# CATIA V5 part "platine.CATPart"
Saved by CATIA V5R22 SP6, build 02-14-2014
Part number: platine
Bounding box of the stored display mesh (mm): x -45 to 45, y -36 to 36, z 0 to 8
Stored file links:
  C:\Users\kremer\Desktop\demo_5x\platine.CATPart
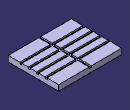
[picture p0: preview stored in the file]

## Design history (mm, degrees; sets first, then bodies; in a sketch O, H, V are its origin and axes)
Body1 (main body)
  Sketch1 on xy-plane, origin (0, 0, 0), H (1, 0, 0), V (0, 1, 0)
    line L1 (45, 36) -> (45, -36)
    line L2 (45, -36) -> (-45, -36)
    line L3 (-45, -36) -> (-45, 36)
    line L4 (-45, 36) -> (45, 36)
    length L1 = 72
    length L4 = 90
    vertical: L1 V, L3 V
    horizontal: L2 H, L4 H
    equidistance: L1 L3 O, L2 L4 O
  Pad1: profile Sketch1, direction (0, 0, 1), length 8
  Sketch2 on end face of Pad1, origin (0, 0, 8), H (1, 0, 0), V (0, 1, 0)
    line L1 (0, 30.8508) -> (0, -26.7938)
    point P1 (0, 30.8508)
    line L2 (31.5327, 18) -> (-33.7368, 18)
    line L3 (28.6352, 6) -> (-29.9244, 6)
    line L4 (27.4152, -6) -> (-35.5668, -6)
    line L5 (24.0602, -18) -> (-23.9769, -18)
    reference projected line E1 (-45, -36) -> (45, -36) from edge [face of Pad1 from Sketch1.L2 | end face of Pad1]
    reference intersected line E2 through (0, 0) direction (-1, 0) from zx-plane
    reference intersected line E3 through (0, 0) direction (-1, 0) from zx-plane
    distance E1 L5 = 18
    distance L5 L2 = 36 (reference)
    distance L5 L4 = 12 {= Sketch2.distance(L5 L2) /3}
    coincidence: P1 V
    vertical: L1 V
    horizontal: L2 H, L3 H, L4 H, L5 H
    symmetry: L2 L5 E2, L4 L3 E3
  Pocket1: profile Sketch2, direction (0, 0, -1), length 2, thin wall 3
